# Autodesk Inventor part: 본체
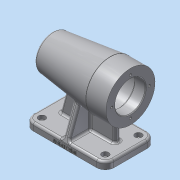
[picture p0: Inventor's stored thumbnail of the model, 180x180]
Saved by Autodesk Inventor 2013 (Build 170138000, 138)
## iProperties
Created: 2018-09
Part Number: 본체
Material: 알루미늄 6061
Document SubType Name: Modeling
Designer: dgall
Density: 2.71 g/cm^3
Mass: 735.464 g
Surface Area: 663.621 cm^2
Volume: 271.389 cm^3
Author: dgall
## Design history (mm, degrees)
sketch "스케치2"
  geometry: L1 (0, 0)-(112, 0); L2 (112, 0)-(112, 70); L3 (112, 70)-(0, 70); L4 (0, 70)-(0, 0)
  constraints: 8 end point, 2 parallel, 1 horizontal, 1 perpendicular
  dimensions: "d0" = 112 distance of L3.end L2.end; "d1" = 70 distance of L2.end L1.end
extrude "돌출1" new body sketch "스케치2" distance "d2" = 10; taper "d3" = 0 deg
node "작업 평면1"
sketch "스케치3"
  geometry: L1 (112, 10)-(112, 0) reference; L2 (112, 0)-(0, 0) reference; L3 (0, 0)-(0, 10) reference; L4 (0, 10)-(112, 10) reference; L5 (0, 74)-(112, 74); L6 (112, 74)-(112, 108); L7 (112, 108)-(84, 108); L8 (3.73, 98.144)-(84, 108); L9 (6, 74)-(6, 84.5); L10 (6, 84.5)-(9, 84.5); L11 (9, 84.5)-(9, 90); L12 (9, 90)-(13, 90); L13 (13, 90)-(13, 91.5); L14 (13, 91.5)-(31, 91.5); L15 (31, 91.5)-(31, 95); L16 (31, 95)-(43, 95); L17 (43, 95)-(43, 98); L18 (43, 98)-(97, 98); L19 (97, 98)-(97, 95); L20 (97, 95)-(112, 95); A1 r 80 centre (80, 74) between (3.73, 98.144) and (0, 74)
  constraints: 32 end point, 10 parallel, 5 perpendicular, 3 point on line, 2 point on circle, 1 centre point, 1 vertical alignment
  dimensions: "d4" = 112 distance of L5.start L5.end; "d5" = 74 distance between parallel lines of L2 L5; "d6" = 80 radius of A1; "d7" = 7 deg angle of L7 L8; "d8" = 68 diameter of L7 L5; "d9" = 28 distance of L6.end L7.end; "d10" = 21 diameter of L10 L5; "d11" = 32 diameter of L12 L5; "d12" = 35 diameter of L14 L5; "d13" = 42 diameter of L16 L5; "d14" = 48 diameter of L18 L5; "d15" = 42 diameter of L20 L5; "d16" = 3 distance of L9.end L10.end; "d17" = 4 distance of L11.end L12.end; "d18" = 18 distance of L13.end L14.end; "d19" = 12 distance of L15.end L16.end; "d20" = 54 distance of L17.end L18.end; "d21" = 15 distance of L19.end L20.end
  node "절단 모서리 투영1"
revolve "회전1" stored, may be unused: angle "d22" = 90 deg
sketch "스케치4"
  geometry: L1 (112, 10)-(112, 0) reference; L2 (112, 0)-(0, 0) reference; L3 (0, 0)-(0, 10) reference; L4 (0, 10)-(112, 10) reference; L5 (3.73, 98.144)-(84, 108) reference; L6 (84, 108)-(112, 108) reference; L7 (112, 108)-(112, 40) reference; L8 (112, 40)-(84, 40) reference; L9 (84, 40)-(3.73, 49.856) reference; L10 (18, 10)-(31.397, 60); L11 (31.397, 60)-(94, 60); L12 (18, 10)-(94, 10); L13 (94, 60)-(94, 10); A1 r 80 centre (80, 74) between (3.73, 98.144) and (3.73, 49.856) reference
  constraints: 8 end point, 2 point on line, 1 parallel, 1 perpendicular
  dimensions: "d23" = 18 distance between parallel lines of L1 L13; "d24" = 18 distance from line of L10.start L3; "d25" = 105 deg angle of L10 L4; "d26" = 50 distance of L11.end L12.end
extrude "돌출2" join sketch "스케치4" stored distance "d27" = 8; taper "d28" = 0 deg
node "작업 평면2"
fillet "모깎기1" dims "d43" = 12
revolve "회전2" stored, may be unused: angle "d57" = 90 deg
fillet "모깎기3" dims "d58" = 0.3
fillet "모깎기4" dims "d59" = 3
fillet "모깎기5" dims "d60" = 3
sketch "스케치5"
  geometry: L1 (7, 0)-(0, 0) reference; L2 (0, 0)-(0, 70) reference; L3 (0, 70)-(7, 70) reference; L4 (10, 67)-(10, 39) reference; L5 (10, 39)-(43.701, 39) reference; L6 (43.701, 31)-(10, 31) reference; L7 (10, 31)-(10, 3) reference; L8 (8.026, 69.819)-(50.386, 54.401); L9 (8.026, 0.181)-(50.386, 15.599); C1 r 24 at (74, 35) reference; A1 r 30.562 centre (74, 35) between (43.701, 31) and (43.701, 39) reference; A2 r 3 centre (7, 67) between (10, 67) and (7, 70) reference; A3 r 3 centre (7, 3) between (7, 0) and (10, 3) reference
  constraints: 4 end point, 4 point on circle, 2 tangent
  dimensions: "d61" = 20 deg angle of L8 L3; "d62" = 20 deg angle of L9 L1
  node "절단 모서리 투영3"
feature "리브5" dims "d63" = 1, "d64" = 8, "d65" = 0, "d66" = 0, "d67" = 1, "d68" = 1
feature "리브6" dims "d69" = 1, "d70" = 8, "d71" = 0, "d72" = 0, "d73" = 1, "d74" = 1
sketch "스케치6" dims "d75" = 52
  geometry: C1 r 21 at (0, 0) reference; C2 r 34 at (0, 0) reference; 3 further points
  constraints: 2 horizontal alignment, 1 coincident, 2 other
hole "구멍1" sketch "스케치6" at (-26, 0) diameter "d76" = 3.242; stored, may be unused: countersink angle "d80" = 90 deg, drill point angle "d82" = 118 deg; dims "d77" = 8, "d78" = 4, "d79" = 2, "d81" = 11
sketch "스케치7"
  geometry: L1 (52, 39)-(52, 67) reference; L2 (52, 67)-(52, 69.101) reference; L3 (52, 69.101)-(60, 69.101) reference; L4 (60, 69.101)-(60, 67) reference; L5 (60, 67)-(60, 39) reference; L6 (60, 39)-(94, 39) reference; L7 (94, 39)-(94, 31) reference; L8 (94, 31)-(60, 31) reference; L9 (60, 31)-(60, 3) reference; L10 (60, 3)-(60, 0.899) reference; L11 (60, 0.899)-(52, 0.899) reference; L12 (52, 0.899)-(52, 3) reference; L13 (52, 3)-(52, 31) reference; L14 (52, 31)-(18, 31) reference; L15 (18, 31)-(18, 39) reference; L16 (18, 39)-(52, 39) reference; L17 (52, 67)-(12, 67) reference; L18 (3, 58)-(3, 12) reference; L19 (12, 3)-(52, 3) reference; L20 (100, 67)-(60, 67) reference; L21 (109, 12)-(109, 58) reference; L22 (60, 3)-(100, 3) reference; A1 r 9 centre (12, 58) between (12, 67) and (3, 58) reference; A2 r 9 centre (12, 12) between (3, 12) and (12, 3) reference; A3 r 9 centre (12, 58) between (12, 67) and (3, 58) reference; A4 r 9 centre (12, 12) between (3, 12) and (12, 3) reference; A5 r 9 centre (100, 58) between (109, 58) and (100, 67) reference; A6 r 9 centre (100, 12) between (100, 3) and (109, 12) reference; 1 further point
hole "구멍2" sketch "스케치7" at (12, 12), (12, 58), (100, 12), (100, 58) diameter "d86" = 5.5; stored, may be unused: countersink angle "d90" = 90 deg, drill point angle "d92" = 118 deg; dims "d87" = 8, "d88" = 9.5, "d89" = 5.4, "d91" = 11
sketch "스케치8"
  geometry: L1 (100, 0)-(100, 7) reference; L2 (100, 0)-(88, 0) reference; 2 further points
  constraints: 1 other
  dimensions: "d93" = 56 distance from line of L1 point (44, 3); "d94" = 3 distance from line of L2 point (44, 3)
feature "엠보싱1" sketch "스케치8" dims "d0" = 112, "d1" = 70, "d4" = 112, "d5" = 74, "d6" = 80, "d7" = 7 deg, "d8" = 68, "d9" = 28, "d10" = 21, "d11" = 32, "d12" = 35, "d13" = 42, "d14" = 48, "d15" = 42, "d16" = 3, "d17" = 4, "d18" = 18, "d19" = 12, "d20" = 54, "d21" = 15, "d95" = 0.5, "d96" = 0
fillet "모깎기6" dims "d97" = 3
fillet "모깎기7" dims "d98" = 3
fillet "모깎기8" dims "d99" = 3
fillet "모깎기9" dims "d100" = 3
fillet "모깎기10" dims "d101" = 3
fillet "모깎기11" dims "d102" = 3
chamfer "모따기1" distance "d103" = 1; stored, may be unused: second distance "d104" = 2, angle "d105" = 45 deg
node "솔리드1"
pattern_circular "원형 패턴1" dims angle "d84" = 360 deg
node "절단 모서리 투영2"
node "절단 모서리 투영4"
